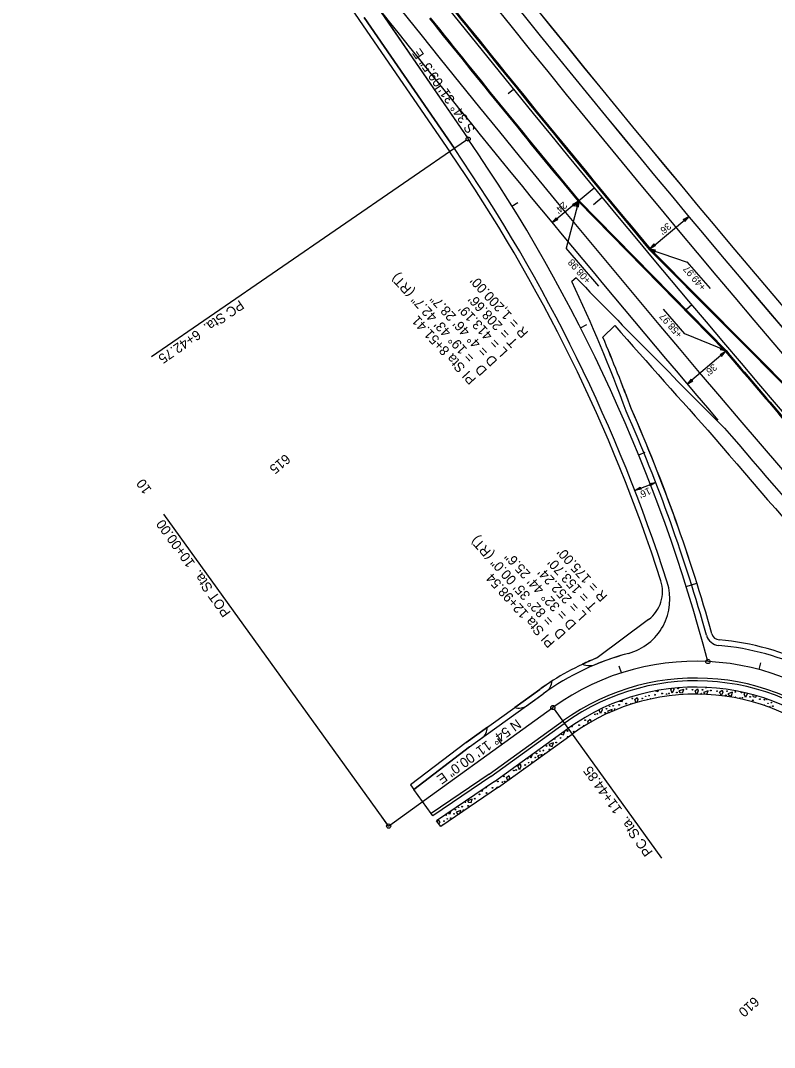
# Model space of a CAD drawing. Extents: x 1262642 to 1268358, y 767825 to 773481.
# Drawn here: x 1265846 to 1266385, y 772149 to 772883 of the extents above; entities that cross this region are included whole.
import ezdxf

# ---------------------------------------------------------------- set-up
doc = ezdxf.new("R2010")
doc.units = 0
for name, color, linetype in [('Default', 7, 'Continuous'), ('Prop Conc 1ft 6in Curb and Gutter', 7, 'Continuous'), ('Prop Conc 2ft 6in Curb and Gutter', 7, 'Continuous'), ('Prop Conc 4in Sidewalk', 7, 'Continuous'), ('Prop Dimension', 7, 'Continuous'), ('Prop Dimension Text', 7, 'Continuous'), ('Prop EOT', 7, 'Continuous'), ('Prop Horizontal Alignment', 7, 'Continuous'), ('Prop Horizontal Alignment Curve and Spiral Data', 7, 'Continuous'), ('Prop Horizontal Alignment Direction Label', 7, 'Continuous'), ('Prop Horizontal Alignment Station Label', 7, 'Continuous'), ('Prop Horizontal Alignment Tick Label', 7, 'Continuous'), ('Prop Horizontal Alignment Tick Large', 7, 'Continuous'), ('Prop Horizontal Alignment Tick Small', 7, 'Continuous'), ('Prop Lane Lines', 7, 'Continuous'), ('Prop Paved Shoulder', 7, 'Continuous'), ('Prop Shade Light', 7, 'Continuous'), ('Prop Terminator CELL', 7, 'Continuous')]:
    doc.layers.add(name, color=color, linetype=linetype)

msp = doc.modelspace()

# ---------------------------------------------------------------- linework, layer by layer
at = {"layer": 'Default'}
for p, q in [((1266244.84, 772753.57), (1266256.41, 772763.12)), ((1266244.84, 772753.57), (1266226.34, 772738.29)), ((1266296.36, 772719.68), (1266324.01, 772742.74)), ((1266350.39, 772646.13), (1266322.93, 772622.85)), ((1266285.45, 772546.81), (1266300.37, 772552.58))]:
    msp.add_line(p, q, dxfattribs=at)
at = {"layer": 'Prop Conc 1ft 6in Curb and Gutter'}
for p, q in [((1266245.4, 772754.07), (1266350.94, 772646.64)), ((1266401.77, 772612.45), (1266295.81, 772719.17))]:
    msp.add_line(p, q, dxfattribs=at)
for centre, radius, start, end in [((1275047.31, 780021.23), 11397.75, 218.697492, 219.840867), ((1275045.61, 780019.75), 11412, 218.698035, 219.543975), ((1275047.31, 780021.23), 11402.25, 220.298228, 220.945622)]:
    msp.add_arc(centre, radius, start, end, dxfattribs=at)
at = {"layer": 'Prop Conc 2ft 6in Curb and Gutter'}
for p, q in [((1266300.19, 772403.43), (1266300.2, 772403.42)), ((1266300.2, 772403.42), (1266302, 772403.05)), ((1266302, 772403.05), (1266302.29, 772403.82)), ((1266311.15, 772404.49), (1266311.91, 772405.17)), ((1266312.23, 772401.81), (1266311.15, 772404.49)), ((1266313.36, 772404.46), (1266312.23, 772401.81)), ((1266313.07, 772405.3), (1266313.36, 772404.46)), ((1266320.43, 772404.55), (1266317.06, 772403.41)), ((1266317.06, 772403.41), (1266317.7, 772402.42)), ((1266317.7, 772402.42), (1266319.51, 772402.05)), ((1266319.51, 772402.05), (1266320.43, 772404.55)), ((1266328.66, 772403.49), (1266330.34, 772404.99)), ((1266329.59, 772401.17), (1266328.66, 772403.49)), ((1266330.87, 772403.46), (1266329.89, 772401.16)), ((1266330.34, 772404.99), (1266330.87, 772403.46)), ((1266337.94, 772403.54), (1266334.57, 772402.41)), ((1266334.57, 772402.41), (1266335.21, 772401.42)), ((1266335.21, 772401.42), (1266337.02, 772401.04)), ((1266337.02, 772401.04), (1266337.94, 772403.54)), ((1266346.16, 772402.49), (1266347.85, 772403.99)), ((1266347.14, 772400.07), (1266346.16, 772402.49)), ((1266348.37, 772402.45), (1266347.34, 772400.04)), ((1266347.85, 772403.99), (1266348.37, 772402.45)), ((1266355.44, 772402.54), (1266352.07, 772401.4)), ((1266352.07, 772401.4), (1266352.72, 772400.42)), ((1266352.72, 772400.42), (1266354.52, 772400.04)), ((1266354.52, 772400.04), (1266355.44, 772402.54)), ((1266363.67, 772401.49), (1266364.41, 772402.15)), ((1266364.75, 772398.81), (1266363.67, 772401.49)), ((1266365.88, 772401.45), (1266364.75, 772398.81)), ((1266365.75, 772401.82), (1266365.88, 772401.45)), ((1266370.3, 772400.65), (1266369.58, 772400.4)), ((1266369.58, 772400.4), (1266370.22, 772399.42)), ((1266372.03, 772399.04), (1266372.41, 772400.07)), ((1266274.49, 772396.29), (1266274.57, 772396.18)), ((1266274.57, 772396.18), (1266276.37, 772395.8)), ((1266276.37, 772395.8), (1266276.86, 772397.12)), ((1266285.52, 772397.25), (1266287.21, 772398.75)), ((1266286.44, 772394.97), (1266285.52, 772397.25)), ((1266287.73, 772397.21), (1266286.82, 772395.09)), ((1266287.21, 772398.75), (1266287.73, 772397.21)), ((1266294.8, 772397.3), (1266293.57, 772396.89)), ((1266294.76, 772397.19), (1266294.8, 772397.3)), ((1266370.22, 772399.42), (1266372.03, 772399.04)), ((1266260.97, 772387.33), (1266259.91, 772389.96)), ((1266262.1, 772389.97), (1266260.97, 772387.33)), ((1266261.78, 772390.9), (1266262.1, 772389.97)), ((1266269.17, 772390.06), (1266265.8, 772388.92)), ((1266265.8, 772388.92), (1266266.44, 772387.94)), ((1266266.44, 772387.94), (1266267.07, 772387.81)), ((1266268.59, 772388.5), (1266269.17, 772390.06)), ((1266382.33, 772392.3), (1266381.22, 772391.92)), ((1266382.08, 772391.62), (1266382.33, 772392.3)), ((1266182.39, 772342.27), (1266234.98, 772380.22)), ((1266251.77, 772381.76), (1266253.45, 772383.26)), ((1266252.38, 772380.23), (1266251.77, 772381.76)), ((1266253.45, 772383.26), (1266253.98, 772381.73)), ((1266253.98, 772381.73), (1266253.64, 772380.95)), ((1266185.03, 772338.62), (1266237.62, 772376.58)), ((1266187.95, 772334.57), (1266240.54, 772372.52)), ((1266232.44, 772372.84), (1266232.69, 772372.45)), ((1266232.69, 772372.45), (1266234.5, 772372.07)), ((1266235.42, 772374.57), (1266234.33, 772374.21)), ((1266234.5, 772372.07), (1266235.42, 772374.57)), ((1266227.29, 772366.33), (1266223.92, 772365.19)), ((1266223.92, 772365.19), (1266224.57, 772364.2)), ((1266224.57, 772364.2), (1266226.37, 772363.83)), ((1266226.37, 772363.83), (1266227.29, 772366.33)), ((1266210.97, 772355.35), (1266210.35, 772356.9)), ((1266212.1, 772357.99), (1266210.97, 772355.35)), ((1266212.05, 772358.13), (1266212.1, 772357.99)), ((1266219.17, 772358.08), (1266215.8, 772356.94)), ((1266215.8, 772356.94), (1266216.44, 772355.96)), ((1266216.44, 772355.96), (1266217.34, 772355.77)), ((1266218.68, 772356.74), (1266219.17, 772358.08)), ((1266201.77, 772349.79), (1266203.45, 772351.28)), ((1266202.85, 772347.11), (1266201.77, 772349.79)), ((1266203.98, 772349.75), (1266202.85, 772347.11)), ((1266203.45, 772351.28), (1266203.98, 772349.75)), ((1266182.39, 772342.27), (1266140.99, 772314.2)), ((1266193.64, 772341.54), (1266195.33, 772343.04)), ((1266194.54, 772339.32), (1266193.64, 772341.54)), ((1266195.85, 772341.51), (1266195.09, 772339.72)), ((1266195.33, 772343.04), (1266195.85, 772341.51)), ((1266185.03, 772338.62), (1266143.63, 772310.55)), ((1266187.95, 772334.57), (1266146.55, 772306.49)), ((1266185.52, 772333.3), (1266187.21, 772334.8)), ((1266187.21, 772334.8), (1266187.41, 772334.2)), ((1266175.35, 772332.06), (1266176.37, 772331.85)), ((1266176.37, 772331.85), (1266176.82, 772333.06)), ((1266185.64, 772333), (1266185.52, 772333.3)), ((1266169.17, 772326.11), (1266165.8, 772324.97)), ((1266165.8, 772324.97), (1266166.44, 772323.98)), ((1266166.44, 772323.98), (1266168.25, 772323.61)), ((1266168.25, 772323.61), (1266169.17, 772326.11)), ((1266140.99, 772314.2), (1266139.82, 772315.82)), ((1266152.85, 772315.13), (1266152.32, 772316.44)), ((1266153.85, 772317.48), (1266152.85, 772315.13)), ((1266161.05, 772317.86), (1266157.68, 772316.72)), ((1266157.68, 772316.72), (1266158.32, 772315.74)), ((1266158.32, 772315.74), (1266159.75, 772315.44)), ((1266160.29, 772315.81), (1266161.05, 772317.86)), ((1266146.55, 772306.49), (1266143.63, 772310.55)), ((1266144.06, 772309.94), (1266145.33, 772311.06)), ((1266145.85, 772309.53), (1266145.3, 772308.23)), ((1266145.33, 772311.06), (1266145.85, 772309.53))]:
    msp.add_line(p, q, dxfattribs=at)
for centre, radius in [((1266295.62, 772400.11), 0.268), ((1266299.9, 772400.74), 0.292), ((1266304.94, 772401.64), 0.289), ((1266308.21, 772401.21), 0.268), ((1266309.89, 772401.6), 0.268), ((1266315.5, 772402.29), 0.268), ((1266316.42, 772405.22), 0.268), ((1266322.33, 772404.82), 0.285), ((1266326.79, 772404.32), 0.268), ((1266333.93, 772404.22), 0.268), ((1266339.84, 772403.81), 0.285), ((1266344.3, 772403.32), 0.268), ((1266350.52, 772400.28), 0.268), ((1266351.44, 772403.22), 0.268), ((1266357.34, 772402.81), 0.285), ((1266361.81, 772402.32), 0.268), ((1266267.55, 772392.4), 0.18), ((1266269.99, 772392.87), 0.268), ((1266274.27, 772393.5), 0.292), ((1266279.31, 772394.39), 0.289), ((1266283.66, 772398.08), 0.268), ((1266290.79, 772397.98), 0.268), ((1266293.18, 772399.64), 0.18), ((1266360.73, 772398.21), 0.268), ((1266362.41, 772398.6), 0.268), ((1266368.02, 772399.28), 0.268), ((1266369.92, 772396.73), 0.292), ((1266374.97, 772397.63), 0.289), ((1266378.24, 772397.21), 0.268), ((1266380.72, 772394.63), 0.18), ((1266383.15, 772395.1), 0.268), ((1266384.23, 772392.57), 0.285), ((1266256.95, 772386.73), 0.268), ((1266258.63, 772387.12), 0.268), ((1266264.24, 772387.8), 0.268), ((1266265.16, 772390.73), 0.268), ((1266271.07, 772390.33), 0.285), ((1266240.51, 772378.01), 0.292), ((1266245.56, 772378.91), 0.289), ((1266248.83, 772378.48), 0.268), ((1266249.9, 772382.59), 0.268), ((1266237.32, 772374.84), 0.285), ((1266237.44, 772370.66), 0.289), ((1266241.78, 772374.35), 0.268), ((1266222.37, 772364.07), 0.268), ((1266228.11, 772369.14), 0.268), ((1266229.19, 772366.6), 0.285), ((1266232.39, 772369.77), 0.292), ((1266214.24, 772355.82), 0.268), ((1266215.16, 772358.76), 0.268), ((1266217.55, 772360.42), 0.18), ((1266219.99, 772360.89), 0.268), ((1266224.27, 772361.52), 0.292), ((1266207.04, 772350.51), 0.268), ((1266208.63, 772355.14), 0.268), ((1266209.43, 772352.17), 0.18), ((1266211.87, 772352.65), 0.268), ((1266191.78, 772342.37), 0.268), ((1266198.83, 772346.51), 0.268), ((1266200.51, 772346.9), 0.268), ((1266183.66, 772334.13), 0.268), ((1266187.44, 772338.69), 0.289), ((1266190.71, 772338.26), 0.268), ((1266192.38, 772338.65), 0.268), ((1266171.07, 772326.38), 0.285), ((1266174.27, 772329.54), 0.292), ((1266179.31, 772330.44), 0.289), ((1266159.43, 772320.2), 0.18), ((1266161.87, 772320.67), 0.268), ((1266164.24, 772323.85), 0.268), ((1266166.14, 772321.3), 0.292), ((1266151.31, 772311.95), 0.18), ((1266153.74, 772312.43), 0.268), ((1266156.12, 772315.6), 0.268), ((1266157.04, 772318.54), 0.268), ((1266162.95, 772318.13), 0.285), ((1266148.92, 772310.29), 0.268)]:
    msp.add_circle(centre, radius, dxfattribs=at)
for centre, radius, start, end in [((1266329.2, 772249.67), 161, 43.27575, 125.81667), ((1266329.2, 772249.67), 156.5, 43.37416, 125.81667), ((1266329.2, 772249.67), 151.5, 43.48861, 125.81667), ((1266333.01, 772401.29), 0.268, 309.67777, 185.66653), ((1266333.01, 772401.29), 0.268, 185.66653, 227.42884), ((1266336.32, 772405.88), 0.18, 138.02574, 350.03217), ((1266336.32, 772405.88), 0.18, 350.03217, 38.9775), ((1266282.58, 772393.97), 0.268, 47.88793, 230.60687), ((1266282.58, 772393.97), 0.268, 343.07386, 47.88793), ((1266284.26, 772394.36), 0.268, 8.16401, 205.21676), ((1266296.7, 772397.57), 0.285, 34.28855, 181.96462), ((1266296.7, 772397.57), 0.285, 21.0886, 34.28855), ((1266357.46, 772398.63), 0.289, 321.04769, 195.2576), ((1266378.33, 772392.97), 0.268, 34.19955, 163.70586), ((1266378.33, 772392.97), 0.268, 337.02882, 34.19955), ((1266379.92, 772397.6), 0.268, 139.82481, 0.75494), ((1266250.51, 772378.87), 0.268, 77.77337, 166.28236), ((1266259.43, 772384.15), 0.18, 16.26993, 217.62192), ((1266221.07, 772358.35), 0.285, 54.83006, 196.80327), ((1266206.95, 772354.75), 0.268, 283.57857, 328.05477), ((1266198.92, 772342.27), 0.268, 75.82738, 175.80595), ((1266206.12, 772347.58), 0.268, 53.26238, 198.37095), ((1266179.19, 772334.62), 0.285, 206.56411, 41.7201), ((1266175.53, 772325.88), 0.268, 88.40797, 159.88182), ((1266150.51, 772314.92), 0.268, 149.70178, 98.58244), ((1266148, 772307.36), 0.268, 54.19904, 194.09075)]:
    msp.add_arc(centre, radius, start, end, dxfattribs=at)
at = {"layer": 'Prop Conc 4in Sidewalk'}
for p, q in [((1266185.03, 772338.62), (1266237.62, 772376.58)), ((1266187.95, 772334.57), (1266240.54, 772372.52)), ((1266185.03, 772338.62), (1266143.63, 772310.55)), ((1266187.95, 772334.57), (1266146.55, 772306.49)), ((1266146.55, 772306.49), (1266143.63, 772310.55))]:
    msp.add_line(p, q, dxfattribs=at)
for radius, start in [(156.5, 43.37416), (151.5, 43.48861)]:
    msp.add_arc((1266329.2, 772249.67), radius, start, 125.81667, dxfattribs=at)
at = {"layer": 'Prop Dimension'}
for p, q in [((1266245.42, 772754.05), (1266236.45, 772720.12)), ((1266259.72, 772692.81), (1266236.45, 772720.12)), ((1266295.82, 772719.24), (1266322.81, 772710.17)), ((1266322.76, 772710.23), (1266339.45, 772691.17)), ((1266321.19, 772658.73), (1266306.05, 772676.51)), ((1266350.94, 772646.64), (1266321.19, 772658.73))]:
    msp.add_line(p, q, dxfattribs=at)
at = {"layer": 'Prop EOT'}
for p, q in [((1266091.84, 772885.1), (1266156.33, 772791.33)), ((1266244.84, 772753.57), (1266350.39, 772646.13)), ((1266402.3, 772612.98), (1266296.36, 772719.68)), ((1266243.45, 772698.83), (1266240.41, 772696.3)), ((1266167.18, 772363.36), (1266219.77, 772401.31)), ((1266181.22, 772343.9), (1266233.81, 772381.85)), ((1266167.18, 772363.36), (1266127.42, 772333.02)), ((1266181.22, 772343.9), (1266139.82, 772315.82)), ((1266139.82, 772315.82), (1266127.42, 772333.02))]:
    msp.add_line(p, q, dxfattribs=at)
for centre, radius, start, end in [((1275047.31, 780021.23), 11361, 216.766365, 222.716029), ((1275047.31, 780021.23), 11397, 218.69746, 219.840704), ((1275045.61, 780019.75), 11412.75, 218.698035, 219.544138), ((1265177.49, 772118.11), 1188, 17.79551, 34.51931), ((1265177.49, 772118.11), 1188, 17.79551, 34.51931), ((1265149.68, 772184.41), 1204.87, 20.34939, 25.14096), ((1274408.34, 780667.93), 11409.29, 224.304767, 225.063416), ((1275047.31, 780021.23), 11403, 220.298366, 220.945622), ((1265177.49, 772118.11), 1204, 15.66544, 23.76964), ((1275047.31, 780021.23), 11439, 220.505091, 222.993587), ((1266270.56, 772468.97), 40, 284.96947, 17.79551), ((1266346.4, 772445.92), 10, 195.66544, 264.99155), ((1266329.2, 772249.67), 187, 104.96947, 125.81667), ((1266329.2, 772249.67), 187, 43.23333, 84.99155), ((1266329.2, 772249.67), 163, 43.23333, 125.81667)]:
    msp.add_arc(centre, radius, start, end, dxfattribs=at)
at = {"layer": 'Prop Horizontal Alignment'}
for p, q in [((1266085.32, 772915.75), (1266166.21, 772798.14)), ((1266085.32, 772915.75), (1266166.21, 772798.14)), ((1266101.72, 772891.9), (1266166.21, 772798.14)), ((1266109.33, 772306.81), (1266226.79, 772391.58))]:
    msp.add_line(p, q, dxfattribs=at)
for centre, radius, start, end in [((1275047.31, 780021.23), 11400, 216.766365, 222.993587), ((1265177.49, 772118.11), 1200, 14.79077, 34.51931), ((1265177.49, 772118.11), 1200, 14.79077, 34.51931), ((1265177.49, 772118.11), 1200, 14.79077, 34.51931), ((1265177.49, 772118.11), 1200, 14.79077, 34.51931), ((1266329.2, 772249.67), 175, 43.23333, 125.81667)]:
    msp.add_arc(centre, radius, start, end, dxfattribs=at)
at = {"layer": 'Prop Horizontal Alignment Station Label'}
for p, q in [((1266164.98, 772797.28), (1265939.63, 772642.3)), ((1266108.46, 772308.03), (1265948.4, 772529.81)), ((1266227.67, 772390.36), (1266304.48, 772283.92))]:
    msp.add_line(p, q, dxfattribs=at)
for centre in [(1266166.21, 772798.14), (1266337.73, 772424.46), (1266226.79, 772391.58), (1266109.33, 772306.81)]:
    msp.add_circle(centre, 1.5, dxfattribs=at)
at = {"layer": 'Prop Horizontal Alignment Tick Large'}
for p, q in [((1266262.11, 772756.22), (1266255.95, 772751.12)), ((1266322.19, 772478.2), (1266329.82, 772480.6)), ((1266109.33, 772306.81), (1266104.65, 772313.3))]:
    msp.add_line(p, q, dxfattribs=at)
at = {"layer": 'Prop Horizontal Alignment Tick Small'}
for p, q in [((1266141.99, 772833.36), (1266146.11, 772836.19)), ((1266198.72, 772833.56), (1266194.84, 772830.41)), ((1266197.52, 772750.21), (1266201.77, 772752.84)), ((1266326.18, 772679.43), (1266322.35, 772676.21)), ((1266246.59, 772663.11), (1266251.05, 772665.38)), ((1266288.25, 772572.23), (1266292.88, 772574.12)), ((1266374.43, 772418.72), (1266375.73, 772423.55)), ((1266275.82, 772416.33), (1266274.29, 772421.09)), ((1266190.42, 772365.33), (1266187.5, 772369.39))]:
    msp.add_line(p, q, dxfattribs=at)
at = {"layer": 'Prop Lane Lines'}
for radius, start, end in [(11373, 216.364944, 223.132748), (11427, 216.367499, 223.547684), (11439, 216.766365, 220.467863)]:
    msp.add_arc((1275047.31, 780021.23), radius, start, end, dxfattribs=at)
at = {"layer": 'Prop Paved Shoulder'}
for p, q in [((1266088.54, 772882.83), (1266153.03, 772789.07)), ((1266271.14, 772664.84), (1266262.59, 772656.43)), ((1266295.26, 772454.55), (1266258.44, 772427.08)), ((1266164.84, 772366.6), (1266217.43, 772404.55)), ((1266164.84, 772366.6), (1266124.99, 772336.2)), ((1266124.99, 772336.2), (1266127.42, 772333.02))]:
    msp.add_line(p, q, dxfattribs=at)
for centre, radius, start, end in [((1275047.31, 780021.23), 11351, 216.766365, 222.716029), ((1265177.49, 772118.11), 1184, 17.91301, 34.51931), ((1274807.64, 780169.8), 11366.44, 221.320677, 221.859349), ((1265149.68, 772184.41), 1208.87, 20.34939, 22.98346), ((1265177.49, 772118.11), 1208, 15.66544, 23.76964), ((1275047.31, 780021.23), 11449, 220.505091, 223.202447), ((1266280.31, 772474.59), 25, 306.72997, 17.91301), ((1266346.4, 772445.92), 6, 195.66544, 264.99155), ((1266329.2, 772249.67), 191, 43.23333, 84.99155), ((1266329.2, 772249.67), 191, 111.74417, 125.81667)]:
    msp.add_arc(centre, radius, start, end, dxfattribs=at)
at = {"layer": 'Prop Shade Light'}
for p, q in [((1266040.94, 772952.64), (1266088.54, 772882.83)), ((1266156.33, 772791.33), (1266091.84, 772885.1)), ((1266088.54, 772882.83), (1266153.03, 772789.07)), ((1266243.45, 772698.83), (1266240.41, 772696.3)), ((1266262.59, 772656.43), (1266271.14, 772664.84)), ((1266295.26, 772454.55), (1266258.44, 772427.08)), ((1266217.43, 772404.55), (1266199.49, 772391.61)), ((1266208.32, 772393.04), (1266219.77, 772401.31)), ((1266180, 772377.54), (1266164.84, 772366.6)), ((1266164.84, 772366.6), (1266124.99, 772336.2)), ((1266127.42, 772333.02), (1266167.18, 772363.36)), ((1266167.18, 772363.36), (1266175.85, 772369.61)), ((1266124.99, 772336.2), (1266127.42, 772333.02))]:
    msp.add_line(p, q, dxfattribs=at)
for centre, radius, start, end in [((1275047.31, 780021.23), 11351, 216.765763, 222.716029), ((1275047.31, 780021.23), 11361, 216.765886, 222.716029), ((1265177.49, 772118.11), 1188, 17.79551, 34.51931), ((1265177.49, 772118.11), 1184, 17.91301, 34.51931), ((1265149.68, 772184.41), 1204.87, 20.34939, 25.14096), ((1274408.34, 780667.93), 11409.29, 224.304767, 225.063416), ((1274807.64, 780169.8), 11366.44, 221.320677, 221.859349), ((1265149.68, 772184.41), 1208.87, 20.35505, 22.98346), ((1265177.49, 772118.11), 1204, 15.66544, 23.76964), ((1265177.49, 772118.11), 1208, 15.66544, 23.76398), ((1275047.31, 780021.23), 11439, 220.505091, 222.993587), ((1275047.31, 780021.23), 11449, 220.505091, 223.202447), ((1266270.56, 772468.97), 40, 284.96947, 17.79551), ((1266280.31, 772474.59), 25, 306.72997, 17.91301), ((1266346.4, 772445.92), 6, 195.66544, 264.99155), ((1266346.4, 772445.92), 10, 195.66544, 264.99155), ((1266329.2, 772249.67), 191, 43.23333, 84.99155), ((1266329.2, 772249.67), 187, 104.96947, 112.23572), ((1266329.2, 772249.67), 187, 43.23333, 84.99155), ((1266329.2, 772249.67), 191, 111.74417, 115.21078), ((1266252.76, 772436.65), 15, 250.869, 292.23572), ((1266329.2, 772249.67), 191, 122.63092, 125.81667), ((1266216.22, 772411.05), 10, 304.99408, 356.95174), ((1266329.2, 772249.67), 187, 124.99408, 125.81667), ((1266202.47, 772401.15), 10, 252.68656, 305.81667), ((1266170, 772377.72), 10, 305.81667, 358.94677)]:
    msp.add_arc(centre, radius, start, end, dxfattribs=at)
at = {"layer": 'Prop Terminator CELL'}
for points in [[(1266240.88, 772751.3), (1266244.84, 772753.57), (1266241.86, 772750.07), (1266241.8, 772751.05)], [(1266243.52, 772749.89), (1266245.42, 772754.05), (1266245.04, 772749.47), (1266244.41, 772750.23)], [(1266230.3, 772740.55), (1266226.34, 772738.29), (1266229.32, 772741.78), (1266229.38, 772740.8)], [(1266320.05, 772740.45), (1266324.01, 772742.74), (1266321.04, 772739.23), (1266320.97, 772740.21)], [(1266300.32, 772721.96), (1266296.36, 772719.68), (1266299.33, 772723.19), (1266299.4, 772722.21)], [(1266300.33, 772718.54), (1266295.82, 772719.24), (1266299.85, 772717.04), (1266299.56, 772717.98)], [(1266347.46, 772642.63), (1266350.39, 772646.13), (1266346.42, 772643.81), (1266347.38, 772643.57)], [(1266346.48, 772647.61), (1266350.94, 772646.64), (1266347.05, 772649.08), (1266347.28, 772648.12)], [(1266325.86, 772626.35), (1266322.93, 772622.85), (1266326.9, 772625.16), (1266325.95, 772625.4)], [(1266289.92, 772547.71), (1266285.45, 772546.81), (1266289.38, 772549.19), (1266289.13, 772548.23)], [(1266295.89, 772551.68), (1266300.37, 772552.58), (1266296.44, 772550.2), (1266296.68, 772551.16)]]:
    msp.add_lwpolyline(points, close=True, dxfattribs=at)

# ---------------------------------------------------------------- texts
at = {"layer": 'Prop Dimension Text'}
for s, rotation, p in [("24'", 220.97369, (1266234.38, 772753.66)), ("36'", 220.97369, (1266308.81, 772738.64)), ('+08.98', 131.17534, (1266254.4, 772697.31)), ('+49.97', 130.4683, (1266336.79, 772692.41)), ('+58.97', 131.17534, (1266319.92, 772658.6)), ("36'", 220.97369, (1266341.62, 772637.76)), ("16'", 205.30974, (1266295.54, 772549.18))]:
    msp.add_text(s, height=5, rotation=rotation, dxfattribs=at).set_placement(p)
at = {"layer": 'Prop Horizontal Alignment Curve and Spiral Data'}
for s, rotation, p in [('= 19%%d 43\' 42.7" (RT)', 132.49159, (1266171.3, 772642.04)), ("R = 1,200.00'", 132.49159, (1266209.69, 772659.78)), ('D = 4%%d 46\' 28.7"', 132.49159, (1266187.57, 772639.51)), ("T = 208.66'", 132.49159, (1266202.32, 772653.02)), ('PI Sta 8+51.41', 132.49159, (1266172.37, 772626.5)), ("L = 413.19'", 132.49159, (1266194.95, 772646.27)), ('D', 132.49159, (1266180.2, 772632.76)), ('= 82%%d 35\' 00.0" (RT)', 132.03039, (1266227.78, 772453.75)), ("R = 175.00'", 132.03039, (1266266.31, 772471.19)), ('D = 32%%d 44\' 25.6"', 132.03039, (1266244.03, 772451.1)), ("T = 153.70'", 132.03039, (1266258.88, 772464.49)), ("L = 252.24'", 132.03039, (1266251.46, 772457.79)), ('PI Sta 12+98.54', 132.03039, (1266228.72, 772438.21)), ('D', 132.03039, (1266236.6, 772444.4))]:
    msp.add_text(s, height=7, rotation=rotation, dxfattribs=at).set_placement(p)
at = {"layer": 'Prop Horizontal Alignment Direction Label'}
for s, rotation, p in [('S 34%%d 31\' 09.5" E', 124.51931, (1266171.66, 772805.21)), ('N 54%%d 11\' 00.0" E', 215.81667, (1266200.89, 772383.67))]:
    msp.add_text(s, height=7, rotation=rotation, dxfattribs=at).set_placement(p)
at = {"layer": 'Prop Horizontal Alignment Station Label'}
for s, rotation, p in [('PC Sta.  6+42.75', 214.51931, (1266002.74, 772683.28)), ('POT Sta.  10+00.00', 125.81667, (1265996.7, 772459.46)), ('PC Sta.  11+44.85', 125.81667, (1266298.65, 772288.24))]:
    msp.add_text(s, height=7, rotation=rotation, dxfattribs=at).set_placement(p)
at = {"layer": 'Prop Horizontal Alignment Tick Label'}
for s, rotation, p in [('615', 219.58941, (1266035.44, 772573.31)), ('10', 125.81667, (1265940.04, 772547.38)), ('610', 222.10238, (1266370.6, 772185.28))]:
    msp.add_text(s, height=7, rotation=rotation, dxfattribs=at).set_placement(p)

doc.saveas('drawing.dxf')
